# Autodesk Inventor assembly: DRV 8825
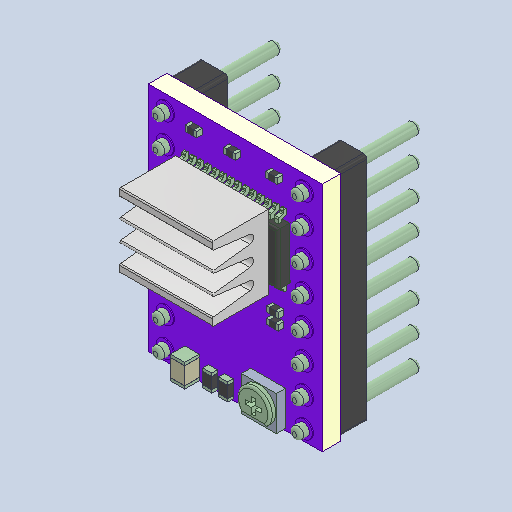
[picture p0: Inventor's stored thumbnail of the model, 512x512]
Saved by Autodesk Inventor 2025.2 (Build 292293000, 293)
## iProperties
Created: 2025-04
Part Number: DRV 8825
Description: PART--DESC
Document SubType Name: Assembly
Designer: BennF
Author: BennF
Revision Number: NONE
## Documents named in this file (9)
- C:\Users\BennF\Nextcloud\Benutzer\CNC JarBeRi\existing parts\Electronics\RepRap A4988 Shied (USE WITHOUT ARDUINO)\reprap-a4988-1.snapshot.1\RepRap\RepRap\DRV 8825_2.iam
- C:\Users\BennF\Nextcloud\Benutzer\CNC JarBeRi\existing parts\Electronics\RepRap A4988 Shied (USE WITHOUT ARDUINO)\reprap-a4988-1.snapshot.1\RepRap\RepRap\DRV 8825 Geometry.ipt
- C:\Users\BennF\Nextcloud\Benutzer\CNC JarBeRi\existing parts\Electronics\RepRap A4988 Shied (USE WITHOUT ARDUINO)\reprap-a4988-1.snapshot.1\RepRap\RepRap\PCB.ipt
- C:\Users\BennF\Nextcloud\Benutzer\CNC JarBeRi\existing parts\Electronics\RepRap A4988 Shied (USE WITHOUT ARDUINO)\reprap-a4988-1.snapshot.1\RepRap\RepRap\SMD Pot.ipt
- C:\Users\BennF\Nextcloud\Benutzer\CNC JarBeRi\existing parts\Electronics\RepRap A4988 Shied (USE WITHOUT ARDUINO)\reprap-a4988-1.snapshot.1\RepRap\RepRap\0603 Resistor.ipt
- C:\Users\BennF\Nextcloud\Benutzer\CNC JarBeRi\existing parts\Electronics\RepRap A4988 Shied (USE WITHOUT ARDUINO)\reprap-a4988-1.snapshot.1\RepRap\RepRap\0805 Capacitor.ipt
- C:\Users\BennF\Nextcloud\Benutzer\CNC JarBeRi\existing parts\Electronics\RepRap A4988 Shied (USE WITHOUT ARDUINO)\reprap-a4988-1.snapshot.1\RepRap\RepRap\0402 Resistor.ipt
- C:\Users\BennF\Nextcloud\Benutzer\CNC JarBeRi\existing parts\Electronics\RepRap A4988 Shied (USE WITHOUT ARDUINO)\reprap-a4988-1.snapshot.1\RepRap\RepRap\DRV8825 IC.ipt
- C:\Users\BennF\Nextcloud\Benutzer\CNC JarBeRi\existing parts\Electronics\RepRap A4988 Shied (USE WITHOUT ARDUINO)\reprap-a4988-1.snapshot.1\RepRap\RepRap\8 pin Header.ipt
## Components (16 placed, 8 different names)
1. DRV 8825 Geometry
2. PCB
3. SMD Pot
4. 0603 Resistor
5. 0603 Resistor:1
6. 0805 Capacitor
7. 0402 Resistor
8. 0402 Resistor:1
9. 0402 Resistor:2
10. 0402 Resistor:3
11. 0402 Resistor:4
12. 0402 Resistor:5
13. 0402 Resistor:6
14. DRV8825 IC
15. 8 pin Header
16. 8 pin Header:1
